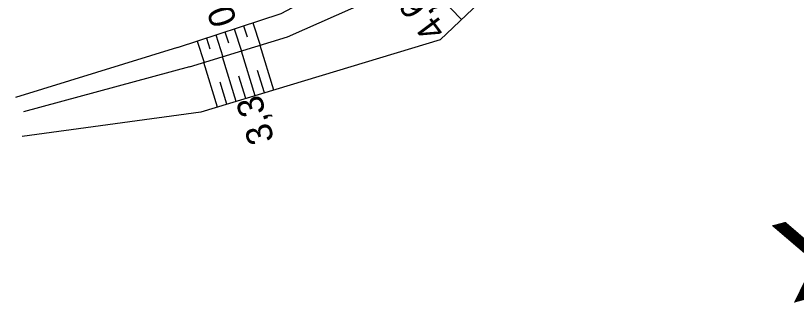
# Model space of a CAD drawing. Extents: x -806456 to -805395, y -1150847 to -1150506.
# Drawn here: x -806206.6 to -806146.8, y -1150752.4 to -1150729.1 of the extents above; entities that cross this region are included whole.
import ezdxf

# ---------------------------------------------------------------- set-up
doc = ezdxf.new("R2010")
doc.units = 0
for name, color, linetype in [('0381KM032-037P - Vrstva 23', 7, 'Continuous'), ('0381KM032-037P - Vrstva 48', 7, 'Continuous'), ('0381KM032-037P - Vrstva 49', 7, 'Continuous'), ('0381KM032-037P - Vrstva 51', 7, 'Continuous')]:
    doc.layers.add(name, color=color, linetype=linetype)

msp = doc.modelspace()

# ---------------------------------------------------------------- linework, layer by layer
at = {"layer": '0381KM032-037P - Vrstva 48'}
for p, q in [((-806172.423, -1150729.435), (-806175.761, -1150725.941)), ((-806189.116, -1150729.927), (-806188.836, -1150730.781)), ((-806188.403, -1150729.694), (-806187.84, -1150731.416)), ((-806190.542, -1150730.393), (-806190.266, -1150731.235)), ((-806189.829, -1150730.16), (-806189.274, -1150731.856)), ((-806192.68, -1150731.092), (-806192.142, -1150732.737)), ((-806191.967, -1150730.859), (-806191.696, -1150731.688)), ((-806191.254, -1150730.626), (-806190.708, -1150732.297)), ((-806186.801, -1150734.851), (-806187.855, -1150731.42)), ((-806189.673, -1150735.718), (-806190.723, -1150732.301)), ((-806188.237, -1150735.284), (-806189.289, -1150731.86)), ((-806191.109, -1150736.152), (-806192.156, -1150732.741)), ((-806187.519, -1150735.068), (-806188.045, -1150733.354)), ((-806188.955, -1150735.501), (-806189.48, -1150733.791)), ((-806190.391, -1150735.935), (-806190.915, -1150734.228))]:
    msp.add_line(p, q, dxfattribs=at)
at = {"layer": '0381KM032-037P - Vrstva 49'}
for p, q in [((-806194.182, -1150731.583), (-806206.578, -1150735.414)), ((-806193.249, -1150733.077), (-806205.97, -1150736.518))]:
    msp.add_line(p, q, dxfattribs=at)
for points in [[(-806193.249, -1150733.077), (-806185.745, -1150730.772), (-806177.154, -1150726.94), (-806171.988, -1150723.234), (-806169.987, -1150720.615)], [(-806194.182, -1150731.583), (-806186.226, -1150728.982), (-806178.594, -1150724.924), (-806174.208, -1150722.043)], [(-806159.8, -1150724.204), (-806168.067, -1150725.273), (-806174.063, -1150731.002)], [(-806174.063, -1150731.002), (-806192.389, -1150736.539), (-806206.086, -1150738.397)]]:
    msp.add_lwpolyline(points, dxfattribs=at)
at = {"layer": '0381KM032-037P - Vrstva 51'}
msp.add_line((-806194.182, -1150731.583), (-806206.578, -1150735.414), dxfattribs=at)
msp.add_lwpolyline([(-806194.182, -1150731.583), (-806186.226, -1150728.982), (-806178.594, -1150724.924), (-806174.208, -1150722.043), (-806171.128, -1150719.056), (-806168.37, -1150714.464), (-806165.452, -1150708.868), (-806162.708, -1150704.236), (-806160.94, -1150702.044), (-806159.44, -1150700.497), (-806157.039, -1150698.345), (-806150.424, -1150694.243), (-806141.479, -1150690.749), (-806131.125, -1150687.358), (-806121.483, -1150684.155)], dxfattribs=at)

# ---------------------------------------------------------------- texts
at = {"layer": '0381KM032-037P - Vrstva 23'}
msp.add_text('zast. Vimperk', height=8, rotation=195, dxfattribs=at).set_placement((-806086.067, -1150728.443))
at = {"layer": '0381KM032-037P - Vrstva 48'}
for s, rotation, p in [('0,6', 108.10376, (-806189.601, -1150729.604)), ('4,6', 126.74, (-806173.521, -1150730.195)), ('3,3', 107.07536, (-806186.742, -1150738.651))]:
    msp.add_text(s, height=2, rotation=rotation, dxfattribs=at).set_placement(p)

doc.saveas('drawing.dxf')
